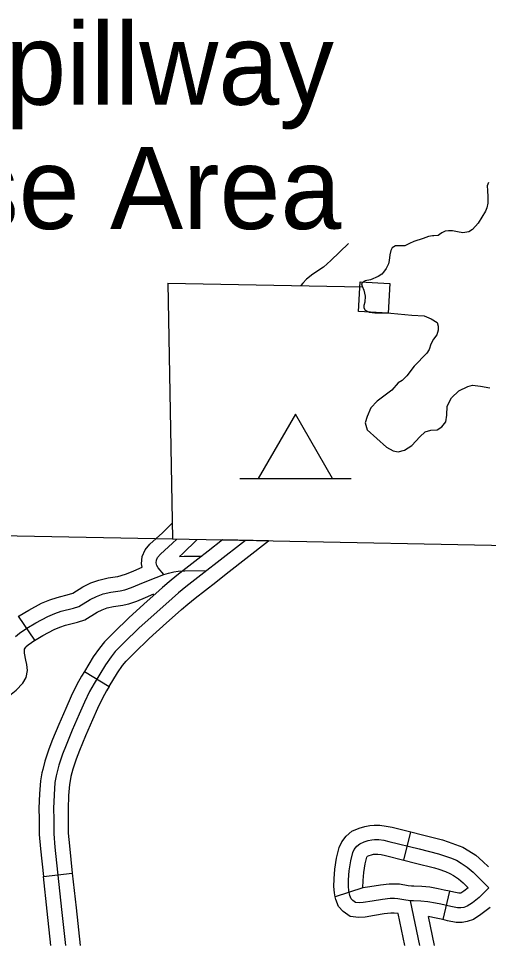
# Model space of a CAD drawing. Extents: x -3711 to 825, y -151 to 1050.
# Drawn here: x -3054.2 to -3027, y 120.4 to 174 of the extents above; entities that cross this region are included whole.
import ezdxf

# ---------------------------------------------------------------- set-up
doc = ezdxf.new("R2010")
doc.units = 0
for name, color, linetype in [('Level 31', 7, 'Continuous'), ('Level 32', 7, 'Continuous'), ('Level 45', 7, 'Continuous'), ('Level 5', 7, 'Continuous'), ('Level 57', 7, 'Continuous'), ('Level 7', 7, 'Continuous'), ('Level 9', 7, 'Continuous')]:
    doc.layers.add(name, color=color, linetype=linetype)

msp = doc.modelspace()

# ---------------------------------------------------------------- linework, layer by layer
at = {"layer": 'Level 31'}
for p, q in [((-3045.151, 139.471), (-3045.151, 139.471)), ((-3050.409, 136.201), (-3048.973, 135.327)), ((-3052.776, 124.351), (-3051.104, 124.53)), ((-3052.776, 124.351), (-3052.776, 124.351))]:
    msp.add_line(p, q, dxfattribs=at)
for points in [[(-3035.128, 160.963), (-3036.166, 159.973), (-3036.587, 159.602), (-3037.205, 159.181), (-3037.573, 158.893), (-3037.785, 158.667), (-3037.899, 158.526)], [(-3041.09, 143.79), (-3042.737, 142.509), (-3043.333, 142.037), (-3044.535, 141.107), (-3044.967, 140.745), (-3045.34, 140.43), (-3046.216, 139.645), (-3047.231, 138.722), (-3048.119, 137.857), (-3048.62, 137.355), (-3048.866, 137.051), (-3049.192, 136.584), (-3049.846, 135.509), (-3050.103, 135.054), (-3050.406, 134.423), (-3050.71, 133.733), (-3051.107, 132.811), (-3051.469, 131.946), (-3051.679, 131.42), (-3051.889, 130.79), (-3052.041, 130.17), (-3052.111, 129.773), (-3052.157, 129.072), (-3052.192, 128.278), (-3052.181, 127.67), (-3052.181, 126.818), (-3052.111, 126.035), (-3051.725, 122.437), (-3051.498, 120.355)], [(-3039.755, 143.765), (-3042.426, 143.816), (-3043.256, 143.171), (-3043.852, 142.699), (-3045.063, 141.762), (-3045.508, 141.388), (-3045.892, 141.064), (-3046.273, 140.722)], [(-3045.151, 139.471), (-3044.789, 139.796), (-3044.426, 140.102), (-3044.007, 140.453), (-3042.815, 141.375), (-3042.218, 141.848), (-3039.755, 143.765)], [(-3046.273, 140.722), (-3046.779, 140.269), (-3047.808, 139.334), (-3048.709, 138.455), (-3049.247, 137.918), (-3049.538, 137.557), (-3049.897, 137.044), (-3050.409, 136.201)], [(-3048.973, 135.327), (-3048.488, 136.124), (-3048.193, 136.546), (-3047.994, 136.792), (-3047.528, 137.259), (-3046.655, 138.11), (-3045.653, 139.021), (-3045.151, 139.471)], [(-3050.409, 136.201), (-3050.572, 135.934), (-3050.849, 135.443), (-3051.17, 134.774), (-3051.481, 134.069), (-3051.881, 133.139), (-3052.247, 132.264), (-3052.468, 131.709), (-3052.697, 131.023), (-3052.817, 130.533)], [(-3048.973, 135.327), (-3049.121, 135.084), (-3049.357, 134.665), (-3049.643, 134.071), (-3049.939, 133.398), (-3050.333, 132.482), (-3050.691, 131.628), (-3050.889, 131.131), (-3051.08, 130.556), (-3051.184, 130.133)], [(-3052.817, 130.533), (-3052.864, 130.344), (-3052.946, 129.874), (-3052.997, 129.119), (-3053.033, 128.288), (-3053.021, 127.662), (-3053.021, 126.78), (-3052.947, 125.953), (-3052.776, 124.351)], [(-3051.184, 130.133), (-3051.218, 129.997), (-3051.275, 129.672), (-3051.318, 129.026), (-3051.351, 128.267), (-3051.34, 127.678), (-3051.34, 126.855), (-3051.274, 126.117), (-3051.104, 124.53)], [(-3051.104, 124.53), (-3050.89, 122.527), (-3050.653, 120.355)], [(-3052.344, 120.355), (-3052.561, 122.346), (-3052.776, 124.351)]]:
    msp.add_lwpolyline(points, dxfattribs=at)
at = {"layer": 'Level 32'}
for p, q in [((-3031.942, 125.292), (-3031.537, 126.924)), ((-3034.306, 123.683), (-3035.904, 123.161)), ((-3029.297, 123.49), (-3029.678, 121.853))]:
    msp.add_line(p, q, dxfattribs=at)
for points in [[(-3035.904, 123.161), (-3035.95, 123.392), (-3035.985, 123.765), (-3035.97, 124.204), (-3035.927, 124.766), (-3035.825, 125.407), (-3035.68, 126.018), (-3035.525, 126.354), (-3035.267, 126.682), (-3034.942, 126.958), (-3034.52, 127.148), (-3034.201, 127.242), (-3033.905, 127.297), (-3033.657, 127.316), (-3033.316, 127.316), (-3032.952, 127.264), (-3032.609, 127.19), (-3031.537, 126.924)], [(-3031.537, 126.924), (-3030.853, 126.754), (-3029.701, 126.459), (-3029.377, 126.355), (-3028.947, 126.203), (-3028.523, 126.04), (-3028.178, 125.826), (-3027.772, 125.57), (-3027.36, 125.221), (-3027.045, 124.906)], [(-3027.017, 123.687), (-3027.589, 123.122), (-3027.969, 122.82), (-3028.27, 122.624), (-3028.467, 122.558), (-3028.637, 122.532), (-3028.833, 122.532), (-3029.226, 122.611), (-3029.789, 122.742), (-3030.103, 122.807), (-3030.548, 122.886), (-3030.954, 122.925), (-3031.386, 122.938), (-3031.552, 122.942), (-3031.818, 122.977), (-3032.054, 123.017), (-3032.289, 123.056), (-3032.473, 123.069), (-3032.734, 123.069), (-3033.18, 123.017), (-3033.769, 122.925), (-3034.279, 122.833), (-3034.515, 122.82), (-3034.738, 122.846), (-3034.895, 122.951), (-3034.986, 123.056), (-3035.065, 123.253), (-3035.117, 123.515), (-3035.143, 123.79), (-3035.13, 124.157), (-3035.091, 124.668), (-3034.999, 125.244), (-3034.882, 125.742), (-3034.803, 125.912), (-3034.659, 126.096), (-3034.489, 126.24), (-3034.227, 126.358), (-3034.004, 126.423), (-3033.795, 126.463), (-3033.625, 126.476), (-3033.376, 126.476), (-3033.101, 126.437), (-3032.8, 126.371), (-3031.059, 125.939), (-3029.933, 125.65), (-3029.645, 125.559), (-3029.239, 125.415), (-3028.899, 125.283), (-3028.624, 125.113), (-3028.27, 124.89)], [(-3034.306, 123.683), (-3034.291, 124.109), (-3034.255, 124.569), (-3034.174, 125.081), (-3034.083, 125.467), (-3034.081, 125.471), (-3034.051, 125.51), (-3034.036, 125.522), (-3033.934, 125.568), (-3033.808, 125.605), (-3033.685, 125.628), (-3033.592, 125.635), (-3033.436, 125.635), (-3033.25, 125.609), (-3032.991, 125.552), (-3031.942, 125.292)], [(-3031.942, 125.292), (-3031.264, 125.124), (-3030.165, 124.842), (-3029.913, 124.762), (-3029.531, 124.626), (-3029.274, 124.527), (-3029.069, 124.4), (-3028.768, 124.211), (-3028.5, 123.983), (-3028.215, 123.698)], [(-3028.27, 124.89), (-3027.93, 124.602), (-3027.616, 124.288), (-3027.328, 123.999), (-3027.017, 123.687)], [(-3029.297, 123.49), (-3029.608, 123.563), (-3029.944, 123.633), (-3030.434, 123.719), (-3030.901, 123.764), (-3031.364, 123.778), (-3031.487, 123.781), (-3031.693, 123.809), (-3032.19, 123.892), (-3032.443, 123.91), (-3032.784, 123.91), (-3033.293, 123.85), (-3033.908, 123.754), (-3034.306, 123.683)], [(-3028.215, 123.698), (-3028.461, 123.503), (-3028.639, 123.387), (-3028.665, 123.378), (-3028.701, 123.373), (-3028.75, 123.373), (-3029.048, 123.432), (-3029.297, 123.49)], [(-3032.259, 122.211), (-3032.503, 122.229), (-3032.685, 122.229), (-3033.066, 122.184), (-3033.63, 122.096), (-3034.181, 121.997), (-3034.541, 121.977), (-3035.036, 122.035), (-3035.454, 122.314), (-3035.714, 122.611), (-3035.874, 123.012), (-3035.904, 123.161)], [(-3031.014, 120.355), (-3031.552, 122.942)], [(-3026.95, 122.556), (-3027.477, 122.138), (-3027.901, 121.861), (-3028.268, 121.738), (-3028.572, 121.691), (-3028.916, 121.691), (-3029.404, 121.789), (-3029.678, 121.853)], [(-3031.873, 120.355), (-3032.259, 122.211)], [(-3030.156, 120.355), (-3030.503, 122.024)], [(-3029.678, 121.853), (-3029.97, 121.921), (-3030.262, 121.982), (-3030.503, 122.024)]]:
    msp.add_lwpolyline(points, dxfattribs=at)
at = {"layer": 'Level 45'}
msp.add_line((-3053.268, 138.014), (-3054.212, 139.405), dxfattribs=at)
for points in [[(-3047.058, 142.238), (-3047.101, 142.425), (-3047.068, 142.855), (-3046.89, 143.243), (-3046.62, 143.571), (-3045.897, 144.233), (-3045.324, 144.793)], [(-3045.808, 141.808), (-3046.137, 142.196), (-3046.218, 142.337), (-3046.253, 142.488), (-3046.242, 142.64), (-3046.172, 142.792), (-3046.008, 142.991), (-3045.319, 143.622), (-3045.068, 143.868)], [(-3044.911, 142.856), (-3044.741, 143.012), (-3043.889, 143.845)], [(-3044.911, 142.856), (-3044.634, 142.875), (-3043.622, 142.877)], [(-3048.476, 141.703), (-3048.281, 141.747), (-3047.972, 141.846), (-3047.545, 142.031), (-3047.058, 142.238)], [(-3054.397, 138.219), (-3054.166, 138.42), (-3053.734, 138.713), (-3053.21, 139.022), (-3052.517, 139.392), (-3052.116, 139.562), (-3051.746, 139.685), (-3051.037, 139.87), (-3050.728, 139.963), (-3050.081, 140.364), (-3049.711, 140.549), (-3049.325, 140.688), (-3048.878, 140.796), (-3048.339, 140.873), (-3048.061, 140.935), (-3047.676, 141.058), (-3047.213, 141.259), (-3046.705, 141.475), (-3045.808, 141.808), (-3045.548, 141.891), (-3045.24, 141.968), (-3044.975, 142.009), (-3044.604, 142.035), (-3043.333, 142.037)], [(-3054.211, 139.405), (-3054.184, 139.424), (-3053.622, 139.755), (-3052.879, 140.151), (-3052.413, 140.348), (-3051.985, 140.491), (-3051.264, 140.68), (-3051.076, 140.736), (-3050.491, 141.098), (-3050.042, 141.323), (-3049.567, 141.494), (-3049.037, 141.622), (-3048.49, 141.7), (-3048.476, 141.703)], [(-3048.111, 140.062), (-3047.841, 140.122), (-3047.38, 140.27), (-3046.882, 140.486), (-3046.394, 140.693)], [(-3053.285, 138.002), (-3052.799, 138.288), (-3052.154, 138.632), (-3051.818, 138.775), (-3051.506, 138.879), (-3050.81, 139.061), (-3050.38, 139.189), (-3049.671, 139.629), (-3049.379, 139.775), (-3049.084, 139.881), (-3048.72, 139.969), (-3048.188, 140.045), (-3048.111, 140.062)], [(-3057.154, 133.989), (-3056.805, 133.936), (-3056.511, 133.946), (-3056.203, 133.989), (-3055.79, 134.133), (-3055.486, 134.298), (-3055.205, 134.475), (-3054.828, 134.743), (-3054.347, 135.115), (-3053.959, 135.531), (-3053.781, 135.852), (-3053.704, 136.267), (-3053.734, 136.603), (-3053.79, 136.862), (-3053.871, 137.266), (-3053.878, 137.384), (-3053.874, 137.447), (-3053.861, 137.489), (-3053.8, 137.612), (-3053.774, 137.647), (-3053.653, 137.752), (-3053.268, 138.014)]]:
    msp.add_lwpolyline(points, dxfattribs=at)
at = {"layer": 'Level 5'}
msp.add_lwpolyline([(-3167.618, 146.884), (-3127.396, 146.285), (-3068.284, 144.318), (-3045.307, 143.872)], dxfattribs=at)
at = {"layer": 'Level 57'}
msp.add_line((-3041.422, 147.372), (-3034.991, 147.372), dxfattribs=at)
for points in [[(-3034.468, 158.739), (-3032.756, 158.642), (-3032.852, 156.93), (-3034.564, 157.027)], [(-3040.35, 147.372), (-3036.063, 147.372), (-3038.207, 151.084)]]:
    msp.add_lwpolyline(points, close=True, dxfattribs=at)
at = {"layer": 'Level 7'}
for points in [[(-3045.573, 158.675), (-3045.307, 143.872), (-3020.076, 143.383)], [(-3045.573, 158.675), (-3034.34, 158.457)]]:
    msp.add_lwpolyline(points, dxfattribs=at)
at = {"layer": 'Level 9'}
for points in [[(-3027.034, 164.494), (-3027.11, 164.298), (-3027.099, 164.025), (-3027.088, 163.654), (-3027.088, 163.305), (-3027.132, 163.021), (-3027.219, 162.824)], [(-3027.219, 162.824), (-3027.637, 162.132), (-3027.963, 161.778), (-3028.181, 161.642), (-3028.534, 161.587), (-3028.833, 161.642), (-3029.132, 161.696), (-3029.35, 161.696), (-3029.553, 161.667), (-3029.731, 161.587), (-3029.867, 161.478), (-3029.948, 161.424), (-3030.193, 161.397), (-3030.275, 161.397), (-3030.519, 161.37), (-3030.818, 161.261), (-3031.353, 161.078), (-3031.607, 160.961), (-3031.879, 160.825), (-3032.015, 160.825), (-3032.287, 160.825), (-3032.423, 160.825), (-3032.613, 160.716), (-3032.695, 160.553), (-3032.749, 160.308), (-3032.776, 159.982), (-3032.831, 159.791), (-3032.967, 159.519), (-3033.103, 159.301), (-3033.211, 159.192), (-3033.429, 159.056), (-3033.864, 158.866), (-3034.163, 158.811), (-3034.245, 158.757), (-3034.245, 158.757), (-3034.381, 158.621), (-3034.353, 158.485), (-3034.245, 158.267), (-3034.163, 157.913), (-3034.19, 157.559), (-3034.245, 157.369), (-3034.245, 157.233), (-3034.163, 157.097), (-3033.946, 156.988), (-3033.619, 156.961), (-3032.695, 156.934), (-3031.471, 156.825), (-3030.764, 156.77), (-3030.356, 156.607), (-3030.003, 156.389), (-3029.948, 156.172), (-3029.948, 155.954), (-3030.03, 155.682), (-3030.22, 155.437), (-3030.383, 155.137), (-3030.465, 154.838), (-3030.601, 154.62), (-3031.335, 153.858), (-3031.77, 153.314), (-3032.042, 153.042), (-3032.26, 152.906), (-3032.64, 152.47), (-3033.483, 151.844), (-3033.837, 151.463), (-3034.054, 150.946), (-3034.163, 150.593), (-3034.054, 150.184), (-3032.939, 149.177), (-3032.559, 148.96), (-3032.26, 148.905), (-3031.906, 149.014), (-3031.471, 149.286), (-3031.009, 149.776), (-3030.71, 150.075), (-3030.383, 150.157), (-3030.003, 150.184), (-3029.731, 150.348), (-3029.513, 150.647), (-3029.459, 151.028), (-3029.432, 151.545), (-3029.187, 152.035), (-3028.752, 152.443), (-3028.235, 152.688), (-3027.963, 152.77), (-3027.501, 152.715), (-3026.957, 152.606)]]:
    msp.add_lwpolyline(points, dxfattribs=at)

# ---------------------------------------------------------------- texts
at = {"layer": 'Level 7'}
for s, p in [('Spillway', (-3059.199, 168.99)), ('Use Area', (-3061.939, 161.803))]:
    msp.add_text(s, height=4.7343, dxfattribs=at).set_placement(p)

doc.saveas('drawing.dxf')
